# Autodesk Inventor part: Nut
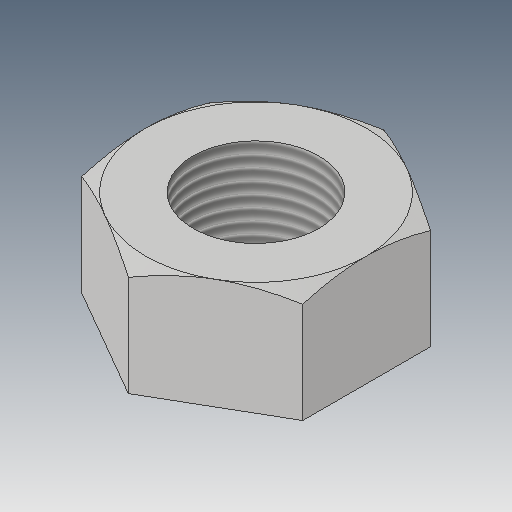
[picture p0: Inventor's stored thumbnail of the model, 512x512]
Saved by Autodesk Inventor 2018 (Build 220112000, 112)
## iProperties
Created: 2016-05
Part Number: Nut
Material: Generic
Document SubType Name: Modeling
Designer: CADCIM
Density: 1 g/cm^3
Appearance: Default
Author: CADCIM
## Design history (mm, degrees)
sketch "Sketch1"
  geometry: L1 (0, -33.255)-(-28.8, -16.628); L2 (-28.8, -16.628)-(-28.8, 16.628); L3 (-28.8, 16.628)-(0, 33.255); L4 (0, 33.255)-(28.8, 16.628); L5 (28.8, 16.628)-(28.8, -16.628); L6 (28.8, -16.628)-(0, -33.255); 2 further points
  constraints: 12 end point, 1 coincident, 13 other
  dimensions: "d0" = 57.6 distance between parallel lines of L2 L5
extrude "Extrusion1" new body sketch "Sketch1" stored distance "d1" = 28.8; taper "d2" = 0 deg
sketch "Sketch2"
  geometry: L1 (0, 33.255)-(-28.8, 16.628) reference; C1 r 28.8 at (0, 0); 1 further point
  constraints: 1 centre point, 1 coincident, 1 tangent
extrude "Extrusion2" sketch "Sketch2" distance "d3" = 28.8; taper "d4" = 60 deg
sketch "Sketch3"
  geometry: 1 further point
hole "Hole1" diameter "d7" = 32.752; stored, may be unused: countersink angle "d11" = 90 deg, drill point angle "d13" = 118 deg; dims "d5" = 10, "d6" = 10, "d8" = 72, "d9" = 4, "d10" = 2, "d12" = 85.1
body "Solid1"
